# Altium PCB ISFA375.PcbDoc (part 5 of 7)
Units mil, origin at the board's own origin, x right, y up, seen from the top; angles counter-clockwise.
Board outline 5615 x 5520 mil, 6 copper layers (Top_SL, GND, POWER, Signal_Layer, GND2, Bottom_SL), stack 60.472 mil thick; 494 components, 307 nets, 1648 pads, 755 vias.
Unrouted connection lines stored in the file: 315.
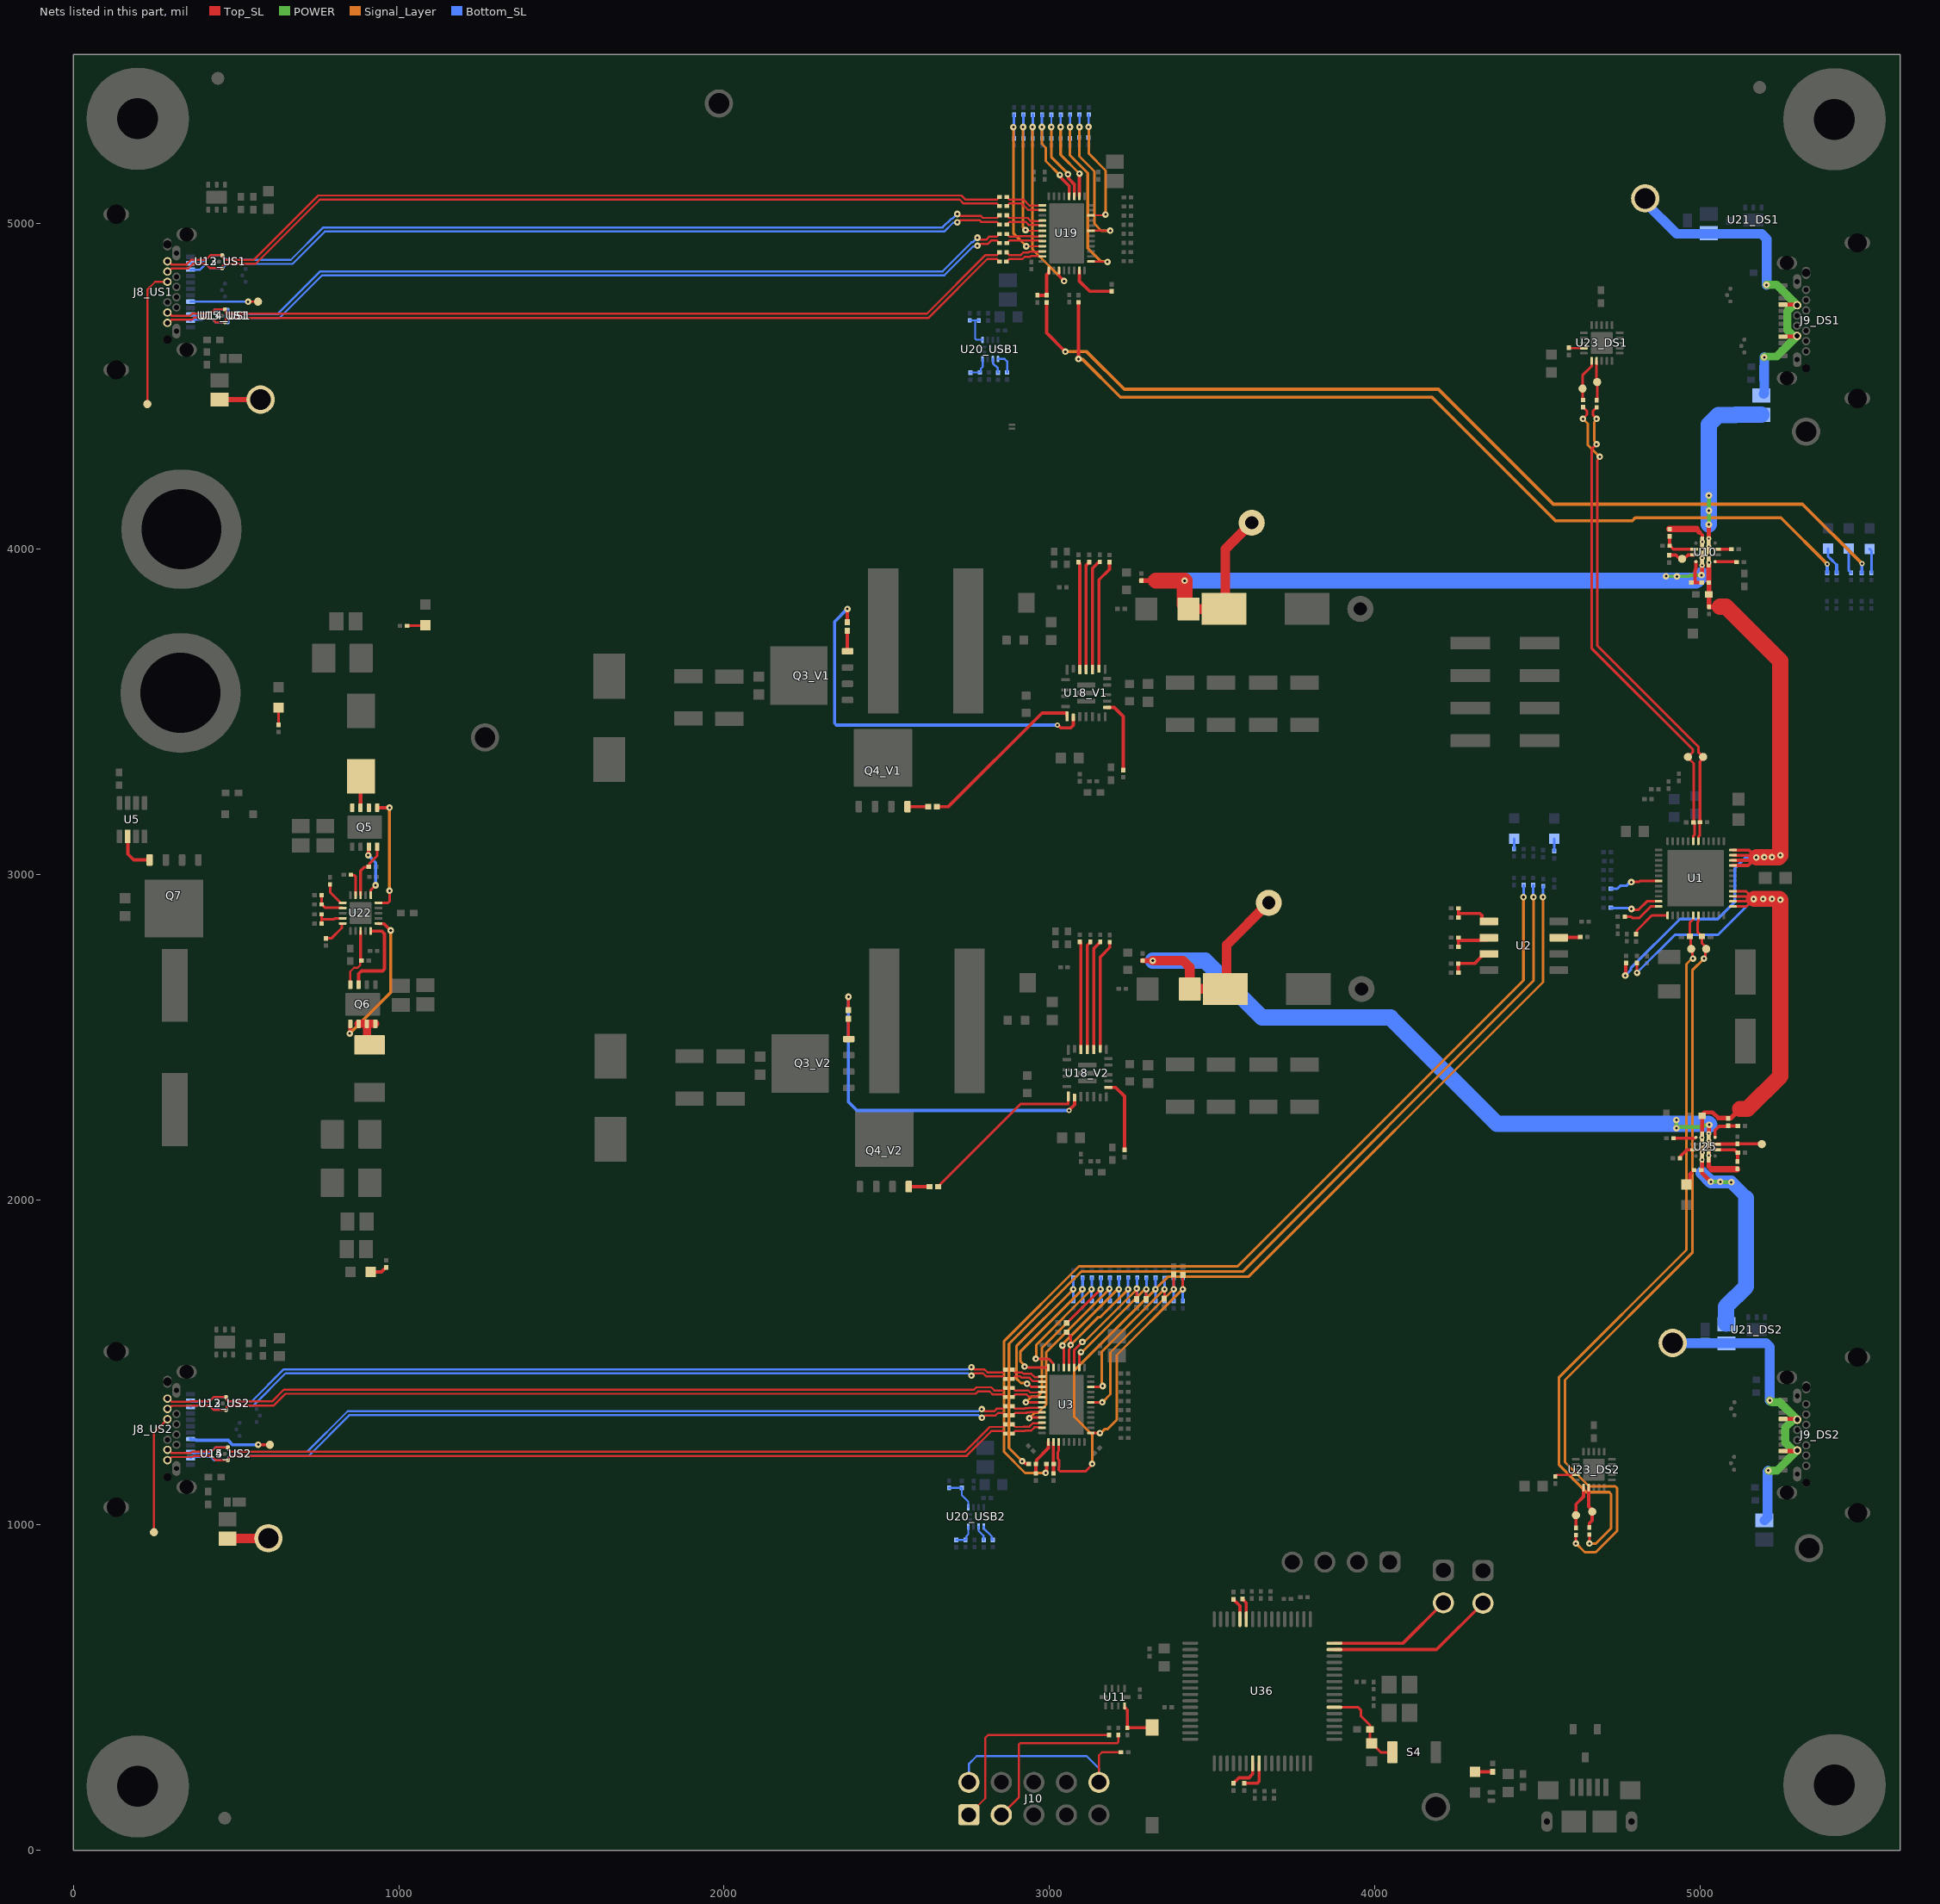
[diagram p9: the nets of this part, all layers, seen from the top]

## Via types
v1: diameter 20, hole 8, Top_SL to Bottom_SL, 628 vias
v2: diameter 19.68, hole 7.87, Top_SL to Bottom_SL, 66 vias
v3: diameter 16, hole 8, Top_SL to Bottom_SL, 23 vias
v4: diameter 16, hole 6, Top_SL to Bottom_SL, tented both sides, 16 vias
v5: diameter 137.8, hole 125.98, Top_SL to Bottom_SL, 8 vias
v6: diameter 50, hole 28, Top_SL to Bottom_SL, 8 vias
v7: diameter 28, hole 16, Top_SL to Bottom_SL, 6 vias

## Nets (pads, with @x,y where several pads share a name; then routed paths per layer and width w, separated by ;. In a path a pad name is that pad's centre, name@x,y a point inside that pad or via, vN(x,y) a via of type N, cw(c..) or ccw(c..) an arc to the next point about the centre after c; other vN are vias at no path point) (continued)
NetD2_2: D2.2 R2.2 | length 54.9
  Top_SL w10: D2.2@4957.96,2046.88 4968.71,2057.63 4968.71,2078.6 4981.41,2091.3 R2.2@4982.2,2091.3
NetD10_2: D10.2 R114.1 | length 52.4
  Top_SL w8: R114.1@630,3460.02 D10.2@630,3512.46
NetD11_2: D11.2 R115.1 | length 57.3
  Top_SL w8: R115.1@1025.51,3764.22 1080.05,3764.22 D11.2@1082.02,3766.19
NetD12_2: D12.2 R116.1 | length 53.3
  Top_SL w10: D12.2@913.97,1777.89 946.91,1777.89 958.91,1789.89 959.7,1789.89 961,1791.19 R116.1@961,1791.98
NetD15_2: D15.2 R110.1 | length 37.9
  Bottom_SL w8: R110.1@4551.61,3071.57 4551.61,3108.89 D15.2@4552,3109.27
NetD16_2: D16.2 R118.1 | length 31.2
  Bottom_SL w8: R118.1@4428.35,3078.21 D16.2@4428.35,3109.39
NetD17_2: D17.2 R156.1 | length 85.4
  Bottom_SL w8: D17.2@5393.39,4001.28 5393.39,3977.36 5399.01,3971.74 5399.43,3971.74 5420,3951.17
  Bottom_SL w10: R156.1@5420,3927.11 5420,3951.17
NetD18_2: D18.2 R158.1 | length 75
  Bottom_SL w8: D18.2@5521.25,4000.58 5526.89,3994.95 R158.1@5526.89,3927.9
NetD20_1: D20.1 R134.2 | length 55.1
  Top_SL w10: D20.1@4307.86,241.33 R134.2@4362.92,241.33
NetD21_2: D21.2 R173.1 | length 77.7
  Bottom_SL w8: D21.2@5456.79,4001.1 5456.79,3934.93 5461.53,3930.2 5462.31,3930.2 5464.61,3927.9 R173.1@5464.61,3927.11
NetJ10_1: J10.1 R155.2 | length 641.8
  Top_SL w6.5: J10.1@2752.24,109.26 2803,160.02 2803,345.98 2811.56,354.55 R155.2@3183.51,354.55
NetJ10_2: J10.2 J10.10 R161.2 | length 679.5
  Top_SL w6.5: J10.10@3152.24,209.26 3152.24,292.34 3161.45,301.56 R161.2@3220.06,301.56
  Bottom_SL w6: J10.2@2752.24,209.26 2752.24,265.48 2776.5,289.75 3114.67,289.75 3152.24,252.18 J10.10@3152.24,209.26
NetJ10_3: J10.3 R157.2 | length 568.5
  Top_SL w6.5: J10.3@2852.24,109.26 2906.68,163.71 2906.68,325.5 2910.49,329.31 3208.04,329.31 3211.85,333.12 R157.2@3211.85,354.55
NetJ13_2: J13.2 U36.47 | length 516.1
  Top_SL w10: U36.47@3875.82,617.15 4190.13,617.15 J13.2@4332.85,759.86
NetJ14_2: J14.2 U36.48 | length 386.6
  Top_SL w10: U36.48@3875.82,636.83 4087.03,636.83 J14.2@4211.08,760.88
NetL5_US1_2: L5_US1.2 TP9_US1.1 | length 126.2
  Top_SL w15: L5_US1.2@448.8,4459.47 TP9_US1.1@575.03,4459.47
NetL5_US2_2: L5_US2.2 TP9_US2.1 | length 125.7
  Top_SL w30: L5_US2.2@473.7,958.47 474.2,958.97 598.53,958.97 TP9_US2.1@599.03,959.47
NetL6_2: L6.2 Q5.6 Q5.7 Q5.8 | length 97.3
  Top_SL w12: Q5.7@882.31,3205.05 882.31,3300.5 L6.2@883.65,3301.83
NetL8_1: L8.1 Q6.6 Q6.7 Q6.8 | length 119.5
  Top_SL w25: Q6.6@876.37,2540.65 Q6.7@901.96,2540.65 ; L8.1@910.42,2475.87 901.96,2484.33 Q6.7@901.96,2540.65 ; Q6.8@927.55,2540.65 Q6.7@901.96,2540.65
NetQ3_V1_4: Q3_V1.4 R67_V1.2 | length 63.4
  Top_SL w10: R67_V1.2@2378.79,3749.19 2379.04,3748.94 2379.04,3686.25 Q3_V1.4@2379.29,3686
NetQ3_V2_4: Q3_V2.4 R67_V2.2 | length 63
  Top_SL w10: R67_V2.2@2382.08,2556.61 2382.08,2495 Q3_V2.4@2383.08,2494
NetQ4_V1_4: Q4_V1.4 R65_V1.2 | length 66
  Top_SL w10: Q4_V1.4@2563.83,3208.4 R65_V1.2@2629.87,3208.4
NetQ4_V2_4: Q4_V2.4 R65_V2.2 | length 66
  Top_SL w10: Q4_V2.4@2567.62,2040.4 R65_V2.2@2633.66,2040.4
NetQ5_3: Q5.3 U22.16 | length 166.8
  Top_SL w8: U22.16@913.97,2936.06 914.07,2936.16 914.07,2951.99 v1(928.72,2966.65)
  Top_SL w10: v1@907.72,3058.96 v1(906.09,3058.96) 907,3059.86 907,3084.06 Q5.3@907.91,3084.97
  Bottom_SL w10: v1(906.09,3058.96) 928.72,3036.33 v1(928.72,2966.65)
NetQ5_4: Q5.4 R14.1 U22.18 | length 177.9
  Top_SL w8: U22.18@882.47,2936.06 882.47,3010.93 894.27,3022.72 906.86,3022.72 R14.1@907.87,3023.72 908.65,3023.72 909.95,3025.02 909.95,3033.63 933.5,3057.17 Q5.4@933.5,3084.97
NetQ5_5: Q5.5 U22.15 | length 361.2
  Top_SL w8: U22.15@937.59,2912.44 966.55,2912.44 971.24,2917.13 v1(971.24,2949.51)
  Top_SL w10: Q5.5@933.5,3205.05 v1(971.24,3205.05)
  Signal_Layer w10: v1(971.24,2949.51) v1(971.24,3205.05)
NetQ6_3: Q6.3 U22.10 | length 273.3
  Top_SL w10: Q6.3@876.37,2660.73 876.37,2694.53 885.43,2703.59 950.24,2703.59 956.09,2709.45 956.09,2817.45 947.72,2825.83 U22.10@913.97,2825.83
NetQ6_4: Q6.4 R15.2 U22.8 | length 187
  Top_SL w6.5: Q6.4@850.78,2660.73 850.78,2701.22 862.69,2713.14 873.51,2713.14 881.59,2721.22 881.59,2732.04 884.29,2734.74 R15.2@885.43,2734.74
  Top_SL w10: U22.8@882.47,2825.83 882.47,2737.26 R15.2@884.64,2735.09
NetQ6_5: Q6.5 U22.11 | length 445.6
  Top_SL w10: v1(849.22,2511.03) 850,2511.81 850,2539.87 Q6.5@850.78,2540.65 ; U22.11@937.59,2849.45 938.65,2848.39 954.41,2848.39 v1(975.11,2827.69)
  Signal_Layer w10: v1(849.22,2511.03) 975.11,2636.93 v1(975.11,2827.69)
NetQ7_4: Q7.4 U5.6 | length 129.1
  Top_SL w10: U5.6@166.79,3117.06 166.79,3062.71 184.92,3044.59 Q7.4@233.84,3044.59 Q7.4@233.72,3044.7
NetR5_2: R5.2 U1.43 | length 157
  Top_SL w8: v1(4788.78,2976.5) 4789.65,2977.38 4812.03,2977.38 4814.78,2980.13 U1.43@4872.83,2980.13
  Bottom_SL w8: R5.2@4725.89,2955.87 4745.98,2955.87 4754.98,2964.87 4773.9,2964.87 4785.53,2976.5 v1(4788.78,2976.5)
NetR11_2: R11.2 U1.47 | length 160
  Top_SL w8: v1(4788.97,2893.86) 4791.27,2891.57 4811.57,2891.57 4837.07,2917.07 U1.47@4872.68,2917.07
  Bottom_SL w8: R11.2@4725.89,2897.87 4727.89,2895.87 4786.97,2895.87 v1(4788.97,2893.86)
NetR16_1: R16.1 R112.2 U22.2 | length 97.7
  Top_SL w8: R112.2@762.72,2936.06 R16.1@762.72,2907.52 764.02,2906.22 764.81,2906.22 773.59,2897.44 826.61,2897.44 U22.2@827.35,2896.69
NetR17_1: R17.1 R25.2 U2.1 | length 138.8
  Top_SL w10: R17.1@4257.24,2867.57 4257.24,2880.08 ; R25.2@4257.24,2895.57 4257.24,2880.08 ; U2.1@4350.93,2855.52 4336.06,2855.52 4329.25,2862.33 4329.25,2874.23 4323.39,2880.08 4257.24,2880.08
NetR18_1: R18.1 R26.2 U2.2 | length 125.3
  Top_SL w10: 4257.02,2797.28 4321.53,2797.28 4322.97,2798.71 4344.12,2798.71 U2.2@4350.93,2805.52 ; R18.1@4257.24,2777.52 4257.24,2789.33 R26.2@4257.24,2805.52
NetR19_1: R19.1 R27.2 U2.3 | length 165.1
  Top_SL w10: R19.1@4256.76,2725.87 4256.89,2725.73 4256.89,2698.27 4257.16,2698 R27.2@4257.94,2698 ; R27.2@4257.81,2697.87 R27.2@4257.02,2697.87 4257.02,2726.13 4306.77,2726.13 4327.39,2746.76 4327.39,2748.71 4334.2,2755.52 U2.3@4350.93,2755.52
NetR20_2: R20.2 U2.7 | length 67.1
  Top_SL w10: U2.7@4565.5,2805.52 4566.52,2806.54 4630.69,2806.54 R20.2@4631.71,2807.56
NetR23_1: R23.1 R111.2 U22.4 | length 96.6
  Top_SL w8: R111.2@762.63,2849.03 762.63,2865.76 ; R23.1@762.63,2877.58 762.63,2865.76 ; U22.4@827.35,2865.19 803.82,2865.19 800.07,2861.44 766.96,2861.44 762.63,2865.76
NetR24_2: R24.2 U22.19 | length 74.3
  Top_SL w8: R24.2@852.73,2999.09 855.03,2996.8 864.34,2996.8 866.72,2994.41 U22.19@866.72,2936.06
NetR28_2: R28.2 U22.1 | length 76.1
  Top_SL w8: R28.2@788.77,2969.17 788.77,2945.28 821.61,2912.44 U22.1@827.35,2912.44
NetR30_2: R30.2 U36.23 | length 104.2
  Top_SL w10: R30.2@3566.07,206.17 3566.07,206.96 3582.37,223.26 3613.57,223.26 3624.83,234.52 U36.23@3624.83,267.74
NetR45_1: R45.1 U36.59 | length 66.9
  Top_SL w10: R45.1@3594,772.98 3594,772.19 3605.15,761.04 U36.59@3605.15,710.65
NetR46_2: R46.2 U36.24 | length 103.6
  Top_SL w10: R46.2@3599.04,206.17 3638.66,206.17 3644.52,212.03 U36.24@3644.52,267.74
NetR47_1: R47.1 U36.60 | length 69.4
  Top_SL w10: R47.1@3566,771.98 3566,771.19 3585.46,751.73 U36.60@3585.46,710.65
NetR63_2: R63.2 R64.2 U10.4 | length 95.2
  Top_SL w10: R64.2@4973.36,3896.96 4988.81,3896.96 ; 4987.4,3896.96 4984.52,3899.84 4984.52,3935.06 4987.4,3937.94 U10.4@4987.4,3961.38 ; 4988.81,3896.88 5001.68,3896.88 R63.2@5001.76,3896.81
NetR65_V1_1: R65_V1.1 U18_V1.1 | length 527.2
  Top_SL w10: R65_V1.1@2653.89,3208.4 2689.76,3208.4 2977.69,3496.33 3052.56,3496.33 3053.13,3495.76 U18_V1.1@3053.13,3487.3
NetR65_V2_1: R65_V2.1 U18_V2.1 | length 529.9
  Top_SL w8: R65_V2.1@2657.68,2040.4 2658.46,2040.4 2662.73,2044.67 2662.73,2045.46 2911.02,2293.74 3057.88,2293.74 3058.08,2293.94 U18_V2.1@3058.08,2318
NetR67_V1_1: R67_V1.1 U18_V1.2 | length 1175.4
  Top_SL w10: R67_V1.1@2378.79,3775.17 v1(2378.79,3815.9) ; v3(3024.6,3459.29) 3026.22,3459.29 3035.35,3450.16 3065.34,3450.16 3073.41,3458.24 3073.41,3482.47 U18_V1.2@3073.49,3482.55
  Bottom_SL w10: v1(2378.79,3815.9) 2339.63,3776.73 2339.63,3465.15 2345.48,3459.29 v3(3024.6,3459.29)
NetR67_V2_1: R67_V2.1 U18_V2.2 | length 1101.3
  Top_SL w10: R67_V2.1@2382.08,2582.59 v1(2382.08,2623.86) ; v3(3060.54,2274.16) 3060.54,2275.78 3077.2,2292.44 3077.2,2314.47 U18_V2.2@3077.28,2314.55
  Bottom_SL w10: v1(2382.08,2623.86) 2382.08,2300.58 2408.49,2274.16 v3(3060.54,2274.16)
NetR71_V1_1: R71_V1.1 U18_V1.14 | length 341
  Top_SL w10: U18_V1.14@3152.23,3632.16 3152.23,3905.42 3184.46,3937.65 R71_V1.1@3184.46,3959.82
NetR71_V2_1: R71_V2.1 U18_V2.14 | length 340
  Top_SL w10: U18_V2.14@3156.02,2464.16 3156.02,2745.88 3185.54,2775.41 R71_V2.1@3185.54,2791.98
NetR73_V1_2: R73_V1.2 U18_V1.8 | length 225.6
  Top_SL w10: U18_V1.8@3177.33,3513.06 3199.63,3513.06 3226.92,3485.77 R73_V1.2@3226.92,3321.02
NetR73_V2_2: R73_V2.2 U18_V2.8 | length 225.6
  Top_SL w10: U18_V2.8@3181.12,2345.06 3203.42,2345.06 3230.71,2317.77 R73_V2.2@3230.71,2153.02
NetR75_V1_2: R75_V1.2 U18_V1.15 | length 338.9
  Top_SL w10: U18_V1.15@3132.54,3629.7 3132.54,3940.49 R75_V1.2@3152.39,3960.34
NetR75_V2_2: R75_V2.2 U18_V2.15 | length 338.9
  Top_SL w10: U18_V2.15@3136.33,2461.7 3136.33,2771.71 3156.18,2791.55 R75_V2.2@3156.18,2792.34
NetR76_V1_2: R76_V1.2 U18_V1.16 | length 334.5
  Top_SL w10: U18_V1.16@3112.86,3629.7 3112.86,3950.14 3122.27,3959.55 R76_V1.2@3122.27,3960.34
NetR76_V2_2: R76_V2.2 U18_V2.16 | length 334.5
  Top_SL w10: U18_V2.16@3116.65,2461.7 3116.65,2782.14 3126.06,2791.55 R76_V2.2@3126.06,2792.34
NetR78_2: R78.2 U19.27 | length 141.4
  Top_SL w10: U19.27@3092.34,4856.27 3092.34,4823.79 3123.53,4792.6 R78.2@3188.31,4792.6
NetR90_USB1_1: R90_USB1.1 R91_USB1.1 U20_USB1.6 | length 73.5
  Bottom_SL w6: R90_USB1.1@2757.5,4542.64 2757.69,4542.83 2785.81,4542.83 2788.84,4545.86 2788.84,4554.3 2794.8,4560.27 U20_USB1.6@2794.8,4584.21
NetR90_USB2_1: R90_USB2.1 R91_USB2.1 U20_USB2.6 | length 73.5
  Bottom_SL w6: R90_USB2.1@2713.5,953.94 2713.7,954.13 2741.81,954.13 2744.84,957.16 2744.84,965.6 2750.81,971.57 U20_USB2.6@2750.81,995.52
NetR103_USB1_2: R103_USB1.2 R104_USB1.2 U20_USB1.9 | length 109.2
  Bottom_SL w6: R104_USB1.2@2755,4702.98 2755.19,4702.79 2771.46,4702.79 ; R103_USB1.2@2783.27,4702.6 2783.08,4702.79 2771.46,4702.79 ; U20_USB1.9@2794.8,4643.27 2774.97,4643.27 2771.46,4646.78 2771.46,4702.79
NetR103_USB2_2: R103_USB2.2 R104_USB2.2 U20_USB2.9 | length 106.8
  Bottom_SL w6: R104_USB2.2@2691.92,1114.09 2730.93,1114.09 R103_USB2.2@2730.93,1113.9 2730.93,1091.72 2750.81,1071.85 U20_USB2.9@2750.81,1054.57
NetR105_1: R105.1 R107.1 U10.2 | length 108.2
  Top_SL w10: R105.1@4906.58,4039.08 R107.1@4906.6,4010.1 4907.39,4010.1 4917.73,3999.76 U10.2@4981.5,3999.76
NetR106_2: R106.2 TP15.1 U10.3 | length 86.6
  Top_SL w10: R106.2@4905.66,3982.05 4906.58,3981.13 4907.5,3982.05 4926,3982.05 4938.05,3970 TP15.1@4945,3970 4950.95,3970 4963,3982.05 U10.3@4981.5,3982.05
NetR108_2: R108.2 U1.1 | length 125.1
  Top_SL w8: R108.2@4803.6,2817.03 4805.9,2819.33 4805.9,2827.9 4851.71,2873.71 U1.1@4900.23,2873.71
NetR109_2: R109.2 U1.48 | length 122.5
  Top_SL w8: R109.2@4766.33,2870.19 4787.97,2870.19 4791.88,2866.28 4813.28,2866.28 4848.32,2901.32 U1.48@4872.68,2901.32
NetR113_2: R113.2 U22.5 | length 78.3
  Top_SL w8: R113.2@775.83,2803.2 792.64,2803.2 824.75,2835.31 824.75,2848.39 825.82,2849.45 U22.5@827.35,2849.45
NetR117_V1_2: R117_V1.2 U18_V1.17 | length 332.2
  Top_SL w10: R117_V1.2@3089.37,3960.34 3089.37,3959.55 3093.17,3955.75 U18_V1.17@3093.17,3629.7
NetR117_V2_2: R117_V2.2 U18_V2.17 | length 332.2
  Top_SL w10: R117_V2.2@3093.16,2792.34 3093.16,2791.55 3096.96,2787.75 U18_V2.17@3096.96,2461.7
NetR139_2: R139.2 U10.9 | length 44.3
  Top_SL w10: U10.9@5052.36,3999.76 R139.2@5096.66,3999.76
NetR144_USB1_1: R144_USB1.1 U20_USB1.4 | length 48.1
  Bottom_SL w6.5: U20_USB1.4@2826.3,4584.21 2826.36,4584.16 2826.36,4570.86 2841.55,4555.67 2841.55,4543.07 R144_USB1.1@2841.98,4542.64
NetR144_USB2_1: R144_USB2.1 U20_USB2.4 | length 48.1
  Bottom_SL w6.5: U20_USB2.4@2782.3,995.52 2782.36,995.46 2782.36,982.16 2797.55,966.97 2797.55,954.37 R144_USB2.1@2797.98,953.94
NetR145_USB1_1: R145_USB1.1 U20_USB1.3 | length 64.7
  Bottom_SL w6.5: U20_USB1.3@2842.05,4584.21 2842.73,4584.21 2862.45,4584.21 2869.95,4576.71 R145_USB1.1@2869.95,4543.02
NetR145_USB2_1: R145_USB2.1 U20_USB2.3 | length 52.7
  Bottom_SL w6.5: U20_USB2.3@2798.05,995.52 2798.74,994.83 2798.74,988.92 2822.91,964.75 2822.91,957.38 R145_USB2.1@2825.96,954.33
NetR149_1: R149.1 R150.1 U3.21 | length 113.4
  Top_SL w10: R150.1@2958.17,1158.76 R149.1@2958.2,1187.74 ; R149.1@2958.2,1187.74 2958.98,1187.74 2960.28,1189.04 2960.28,1199.92 2997.12,1236.75 U3.21@2997.12,1255.56
NetR151_1: R151.1 R152.1 U3.22 | length 96.9
  Top_SL w10: U3.22@3012.12,1254.82 3012.12,1230.54 3011.8,1230.22 3011.8,1188.8 3012.87,1187.74 3012.75,1187.62 3012.75,1159.21 R151.1@3012.31,1158.76
NetR153_1: R153.1 R154.1 U19.21 | length 108
  Top_SL w6: R154.1@2963.31,4780.02 R154.1@2963.47,4780.19 ; R153.1@2991.29,4780.19 R153.1@2991.45,4780.35
  Top_SL w10: R154.1@2963.47,4780.19 R153.1@2991.29,4780.19 ; R153.1@2991.45,4780.35 2991.45,4843.95 2994.96,4847.46 2996.91,4847.46 2997.85,4848.4 U19.21@2997.85,4856.27
NetR159_DS1_2: R159_DS1.2 TP13_DS1.1 U23_DS1.12 | length 121.9
  Top_SL w8: R159_DS1.2@4682.22,4457.77 4683.89,4459.44 TP13_DS1.1@4683.89,4513.37 4682.22,4515.04 U23_DS1.12@4682.22,4578.25
NetR159_DS2_2: R159_DS2.2 TP13_DS2.1 U23_DS2.12 | length 129.9
  Top_SL w10: U23_DS2.12@4657.93,1115.2 4657.93,1058.53 4657.54,1058.14 4657.54,1056.37 4668.29,1045.63 4668.29,1013.6 4659.9,1005.21 R159_DS2.2@4659.9,993.4
NetR160_DS1_2: R160_DS1.2 TP14_DS1.1 U23_DS1.11 | length 132.2
  Top_SL w8: R160_DS1.2@4640.83,4458.29 4638.83,4460.29 4638.83,4534.01 4666.47,4561.65 U23_DS1.11@4666.47,4578.25
NetR160_DS2_2: R160_DS2.2 TP14_DS2.1 U23_DS2.11 | length 133.4
  Top_SL w10: R160_DS2.2@4618.56,991.63 TP14_DS2.1@4618.56,1030.36 4618.56,1063.86 4642.18,1087.48 U23_DS2.11@4642.18,1115.2
NetR162_2: R162.2 S1.2 U11.9 | length 141.5
  Top_SL w10: U11.9@3232.6,438.56 3239.85,431.3 R162.2@3239.85,376.6 3240.64,377.38 S1.2@3316.08,377.38
NetR163_DS1_2: R163_DS1.2 U23_DS1.9 | length 46.8
  Top_SL w6.5: R163_DS1.2@4597.08,4620.18 4599.05,4618.21 4641.75,4618.21 U23_DS1.9@4642.7,4617.27
NetR163_DS2_2: R163_DS2.2 U23_DS2.9 | length 66.1
  Top_SL w6.5: R163_DS2.2@4554.97,1149.54 4554.97,1150.32 4559.22,1154.57 U23_DS2.9@4618.56,1154.57
NetR164_1: R164.1 U10.7 | length 66.6
  Top_SL w10: U10.7@5046.46,3961.38 5111.4,3961.38 R164.1@5112.58,3960.2
NetR166_2: R166.2 R167.2 U25.4 | length 98.5
  Top_SL w10: U25.4@5046.37,2191.53 5046.37,2213.52 5058.18,2225.34 5084.96,2225.34 5086.26,2226.63 R166.2@5086.26,2227.42 5086.75,2226.93 5115.75,2226.93 R167.2@5116.23,2226.45
NetR168_1: R168.1 R170.1 U25.2 | length 94.5
  Top_SL w10: U25.2@5052.28,2153.14 5106.57,2153.14 5113.97,2145.75 5114.76,2145.75 5115.66,2144.84 5115.66,2117.71 R168.1@5115.27,2117.32
NetR169_2: R169.2 TP16.1 U25.3 | length 138.5
  Top_SL w10: U25.3@5052.28,2170.86 5052.35,2170.94 5114.42,2170.94 R169.2@5115.27,2171.78 5189.23,2171.78 TP16.1@5190.08,2170.94
NetR171_2: R171.2 U25.9 | length 55.9
  Top_SL w10: R171.2@4939.56,2127.55 4939.56,2133.42 4959.28,2153.14 U25.9@4981.41,2153.14
NetR172_1: R172.1 U25.7 | length 69.8
  Top_SL w8: R172.1@4918.54,2189.07 4984.31,2189.07 4986.77,2191.53 U25.7@4987.32,2191.53
PA_CC1: C1.2 R159_DS1.1 TP1.1 U1.31 | length 1493.6
  Top_SL w8: v1(4682.22,4322.25) 4666.47,4306.5 4666.47,3695.53 4978.6,3383.4 4978.6,3376.77 TP1.1@4963,3361.17 4963,3359.14 4980.81,3341.33 C1.2@4980.81,3160 ; v1(4682.22,4400.49) 4670.41,4412.3 4670.41,4423.92 4680.13,4433.64 4680.92,4433.64 4682.22,4434.94 R159_DS1.1@4682.22,4435.73 ; U1.31@4979.11,3109.98 4979.11,3118.33 4983.78,3123.01 C1.2@4983.78,3160
  Signal_Layer w8: v1(4682.22,4322.25) 4682.22,4324.96 4675,4332.18 4675,4390.57 4682.22,4397.78 v1(4682.22,4400.49)
PA_CC2: C2.2 R160_DS1.1 TP2.1 U1.30 | length 1510.7
  Top_SL w8: v1(4640.14,4400.49) 4652.64,4412.99 4652.64,4424.44 4642.92,4434.16 4642.13,4434.16 4640.83,4435.46 R160_DS1.1@4640.83,4436.25 ; v1(4691.93,4284) 4691.93,4281.05 4684.19,4273.31 4684.19,3702.94 4995.72,3391.4 4995.72,3374.95 TP2.1@5009.5,3361.17 5009.5,3356.57 4999.87,3346.93 C2.2@4999.87,3160.63 4998.63,3159.39 4998.63,3119.47 4994.94,3115.78 U1.30@4994.87,3102.17 U1.30@4994.87,3102.17
  Signal_Layer w8: v1(4640.14,4400.49) 4655,4385.63 4655,4319.93 4690.93,4284 v1(4691.93,4284)
PA_PPHV: C52_V1.1 R69_V1.2 R77_V1.2 R105.2 TP7_V1.1 U10.5 | length 2770.6
  Top_SL w10: R105.2@4906.58,4061.13 R105.2@4906.58,4061.91 ; 4998.1,4051.38 4998.9,4052.18 ; 4998.93,4052.18 5003.64,4046.92 5004.45,4046.01 5007,4043.16 v4(5007,4022.17) 5007,4020.54 5007.09,4020.45 5007,4020.36 v4(5007,3998)
  Top_SL w12: v1(5004.52,3919.91) 5004.52,3922.07 5007.09,3924.64 U10.5@5007.09,3949.66 ; v4(5006.52,3949.93) 5006.99,3949.93 U10.5@5006.99,3972.59 ; v4(5006.52,3972.59) U10.5@5006.99,3972.59 ; v4(5007,3998) U10.5@5006.99,3972.59
  Top_SL w15: R77_V1.2@3282.73,3902.86 3314.57,3902.86 ; 4989.23,4061.91 4989.59,4061.56 4989.59,4059.89 4998.1,4051.38
  Top_SL w20: R105.2@4906.58,4061.91 4989.23,4061.91
  Top_SL w30: R69_V1.2@3427.9,3815.9 C52_V1.1@3536.79,3815.9 3540.74,3819.85 3540.74,3999.62 TP7_V1.1@3622,4080.88
  Top_SL w50: 3327.36,3902.86 v1(3415.66,3902.86) 3415.66,3830.11 3419.44,3826.33 3419.44,3824.37 R69_V1.2@3427.9,3815.9
  POWER w10: v1(4895.58,3916.51) v1@4895.79,3916.3 ; v1@4896.5,3915.59 v1@4895.79,3916.3 ; v4(5007,4022.17) 5005.85,4021.02 5005.85,3921.23 v1(5004.52,3919.91) 4969.64,3919.91 4965.82,3916.09 v1(4929.02,3916.09) 4928.8,3916.3 v1@4895.79,3916.3
  Bottom_SL w10: v1(5004.52,3919.91) 5005.85,3921.23 v4@5005.85,3949.93 ; v4(5006.52,3949.93) v4(5006.52,3972.59) ; v4@5007,3973.07 v4(5007,3998) v4(5007,4022.17)
  Bottom_SL w50: v1(3415.66,3902.86) 4987.48,3902.86 v1(5004.52,3919.91)
PA_VBUS: C3.1 L2_DS1.1 R1.1 R63.1 R133.2 U1.21 U1.22 U1.23 U1.24 U10.6 | length 2956.1
  Top_SL w10: v1(4770.3,2689.07) 4771.78,2690.54 4771.78,2726.07 R133.2@4773.08,2727.37 ; U1.21@5101.17,3027.37 5148.37,3027.37 v1(5173,3052) 5150.39,3074.61 U1.24@5101.17,3074.61 ; U1.22@5101.17,3043.12 5161.95,3043.12 ; U1.23@5101.17,3058.87 v1@5166.13,3058.87
  Top_SL w12: U10.6@5026.77,3957.86 v4(5027.49,3958.57) ; U10.6@5026.77,3990.66 U10.6@5026.77,3990.91 v4(5026.77,4008.07) 5026.77,4031.91 U10.6@5026.87,4032 ; U10.6@5027.02,3958.82 U10.6@5027.02,3990.66 ; v1(5027,4075.39) 5027.04,4075.34 5027.04,4031.95 v4(5027.09,4031.91) ; 5053.31,3822.61 5057.28,3826.58
  Top_SL w15: R63.1@5027.02,3897 U10.6@5027.02,3951.16 ; C3.1@5027.22,3861 C3.1@5027.49,3861 ; R63.1@5027.49,3896.7 C3.1@5027.49,3861 ; 5053.31,3822.61 R1.1@5027.49,3822.61 C3.1@5027.49,3861
  Top_SL w50: 5061.25,3822.61 5080.32,3822.61 5246.87,3656.06 v1(5246.87,3058.72) 5240.98,3052.82 v1(5221,3052.82) v1(5197.41,3052.82) v1@5173.82,3052.82
  POWER w12: v1(5027.09,4165) 5027.29,4164.8 5027.29,4118.2 5027.24,4118.15 5027.24,4075.63 v1(5027,4075.39) 5027.04,4075.34 5027.04,4032.15 5027.29,4031.91 5027.29,3958.77 v4(5027.49,3958.57)
  Bottom_SL w8: v1(4770.3,2689.07) 4787.19,2705.95 4787.19,2711.47 4938.45,2862.73 5054.4,2862.73 5107.08,2915.42 5107.08,3018.63 5140.45,3052 v1(5173,3052)
  Bottom_SL w12: v1(5027,4075.39) 5027.24,4075.14 5027.24,3958.82 v4(5027.49,3958.57)
  Bottom_SL w50: v1(5027,4075.39) 5027.49,4075.87 v1(5027.49,4118) 5027.49,4164.6 v1(5027.09,4165) 5027.09,4382.9 5056.38,4412.19 5108.73,4412.19 5109.25,4412.71 L2_DS1.1@5188.87,4412.71
  other v4: 5027,3981
PB_CC1: C6.1 R159_DS2.1 TP4.1 U1.6 | length 2285.3
  Top_SL w8: v1(4659.9,943.55) R159_DS2.1@4659.9,970.57 ; v1(4978.6,2741.02) 4978.6,2744.27 4976.25,2746.62 4976.25,2767.75 4971,2773 4971,2808 C6.1@4969,2810 4969,2852.13 4979.13,2862.25 U1.6@4979.13,2873.83
  Signal_Layer w8: v1(4659.9,943.55) 4680.46,943.55 4726.68,989.77 4726.68,1095.35 4720.92,1101.11 4650.37,1101.11 4566.78,1184.7 4566.78,1454.55 4957.96,1845.72 4957.96,2723.79 4963.61,2729.45 4963.79,2729.45 4975.36,2741.02 v1(4978.6,2741.02)
PB_CC2: C7.1 R160_DS2.1 TP5.1 U1.7 | length 2387.9
  Top_SL w8: v1(4618.56,943.55) R160_DS2.1@4618.56,969.58 ; U1.7@4994.87,2873.83 4994.81,2873.76 4994.81,2855.22 4992.12,2852.52 4992.12,2823.1 5006.01,2809.21 5006.01,2788.59 5019,2775.6 TP5.1@5019,2771 5016.13,2768.13 5016.13,2747.64 5012.21,2743.72 v1(5012.21,2741.02)
  Signal_Layer w8: v1(4618.56,943.55) 4645.68,916.43 4679.43,916.43 4744.55,981.55 4744.55,1114.14 4739.87,1118.83 4659.23,1118.83 4585,1193.06 4585,1445.82 4976.17,1837 4976.17,2704.98 v1(5012.21,2741.02)
PB_PPHV: C52_V2.1 R69_V2.2 R77_V2.2 R168.2 TP7_V2.1 U25.5 | length 3111.4
  Top_SL w12: 5027,2102.4 v4(5027,2135.87) 5027.59,2136.46 v4(5027.59,2158.05) 5027.5,2158.15 5027.5,2181.48 5026.95,2182.03 v4(5027,2203) v4(5027,2203) 5027.61,2203.61 5027.61,2229.84 v1(5028.32,2230.55) ; R168.2@5114.97,2094.18 5115.27,2094.48 R168.2@5115.27,2095.27
  Top_SL w15: R77_V2.2@3286.51,2734.86 v1(3317.72,2734.86) ; 5027,2102.4 5035.22,2094.18
  Top_SL w20: 5035.22,2094.18 R168.2@5114.18,2094.18
  Top_SL w30: v1(3317.72,2734.86) 3411.09,2734.86 3431.69,2714.26 R69_V2.2@3431.69,2647.9 C52_V2.1@3540.57,2647.9 3544.53,2651.85 3544.53,2782.95 TP7_V2.1@3674.46,2912.88
  POWER w12: v1(4927.2,2244.94) v1(4927.2,2219.95) 4929.37,2219.95 4933.42,2224.01 5009.2,2224.01 5014.23,2229.04 5026.81,2229.04 v1(5028.32,2230.55) 5027.66,2229.89 5027.66,2203 5027.66,2181.99 5027.66,2158.05 5027.66,2136.53 v4(5027,2135.87)
  Bottom_SL w12: v4(5027,2135.87) 5027.3,2136.16 5027.3,2157.76 v4(5027.59,2158.05) 5027.25,2158.4 5027.25,2181.65 v4(5026.91,2181.99) 5026.95,2182.04 v4(5027,2203) v4(5027,2203) 5027.66,2203.66 5027.66,2229.89 v1(5028.32,2230.55)
  Bottom_SL w50: v1(3317.72,2734.86) 3479.14,2734.86 3653.73,2560.27 4048.74,2560.27 4376.06,2232.94 5025.92,2232.94 v1(5028.32,2230.55)
PB_VBUS: C5.1 L2_DS2.1 R2.1 R146.2 R166.1 U1.13 U1.14 U1.15 U1.16 U25.6 | length 2789.8
  Top_SL w8: R146.2@4805.82,2727.39 4806,2727.2 4806,2698.05 v1(4806.19,2697.87) ; U1.13@5101.13,2901.32 5142.21,2901.32 v1@5158.03,2917.13 ; U1.14@5101.17,2917.13 v1@5158.03,2917.13 ; U1.15@5101.13,2932.82 5146.36,2932.82 5149.74,2931.77 v1@5161.13,2926.16 ; U1.16@5101.13,2948.57 5140.73,2948.57 v1@5161.79,2927.5 ; v1(5165.09,2924.2) v1@5158.03,2917.13
  Top_SL w12: v4(5006.32,2123.13) 5006.32,2082.03 v1(5033.34,2055) ; U25.6@5006.99,2123.13 5006.99,2145.31 U25.6@5007,2162 U25.6@5007,2191.26 ; U25.6@5007.08,2194.85 5007.08,2192.02 v4(5006.32,2191.26) 5006.32,2261.66 5013.34,2268.69 5038.59,2268.69 5056.43,2250.85
  Top_SL w15: 5056.43,2250.85 5094.94,2250.85 5123.1,2279
  Top_SL w25: v1(5165.09,2924.2) v1@5165.71,2924.82 ; v1@5244.05,2924.82 v1(5246.87,2922)
  Top_SL w50: 5123.1,2279 5146,2279 5246.87,2379.87 v1(5246.87,2922) ; v1@5165.71,2924.82 v1(5193.98,2924.82) v1(5221,2924.82) v1@5244.05,2924.82
  POWER w12: v4(5006.32,2123.13) 5006.32,2082.03 v1(5033.34,2055) v1(5062.51,2055) 5063.05,2054.46 5095.54,2054.46 v1(5096.08,2053.92) ; v4@5006.32,2168.74 v4(5006.32,2191.26) ; v4@5006.91,2123.72 v4@5006.91,2168.65
  Bottom_SL w8: v1(4806.19,2697.87) 4922.78,2814.46 5055.35,2814.46 5142.48,2901.59 v1(5165.09,2924.2)
  Bottom_SL w12: 5006.32,2082.03 v4(5006.32,2123.13) v4(5006.32,2191.26) ; L2_DS2.1@5079.69,1618.95 L2_DS2.1@5081.11,1617.53
  Bottom_SL w40: 5006.32,2082.03 v1(5033.34,2055) v1(5062.51,2055) 5095,2055 v1(5096.08,2053.92) 5139,2011
  Bottom_SL w50: L2_DS2.1@5079.69,1618.95 5079.69,1671.05 5141.47,1732.83 5141.47,2005
  other v4: 5006.91,2145.31 5006.82,2168.74
RD1_AEQCFG: R85.1 R99.2 U19.23 | length 625.7
  Top_SL w8: U19.23@3029.35,4856.27 3029.35,4839.88 v1(3045.09,4824.13)
  Signal_Layer w8: v1(2948.06,5297.31) 2948.06,4921.16 v1(3045.09,4824.13) ; v1@2951.5,5297.31 v1@2951.5,5297.66
  Bottom_SL w8: R99.2@2948.74,5262.69 2948.4,5263.04 2948.4,5296.97 v1(2948.06,5297.31) 2948.52,5297.78 2948.52,5334.85 R85.1@2948.99,5335.31
RD1_CEQ0: R83.1 R97.2 U19.38 | length 409.1
  Top_SL w6: U19.38@3127.77,5025.56 3127.96,5025.75 3170.35,5025.75 v1(3172.66,5028.07)
  Signal_Layer w8: v1(3119.95,5297.93) 3120.95,5296.93 3120.95,5215.65 3172.76,5163.84 3172.76,5028.17 v1(3172.66,5028.07)
  Bottom_SL w6: R97.2@3119.95,5264.69 v1(3119.95,5297.93) 3120.45,5298.43 3120.45,5335.14 R83.1@3120.95,5335.64
RD1_CEQ1: R84.1 R98.2 U19.29 | length 598.2
  Top_SL w6: U19.29@3127.77,4883.83 3155.73,4883.83 3156.68,4882.88 3178.44,4882.88 v1(3178.68,4882.64)
  Signal_Layer w8: v1(3063.32,5297.31) 3063.32,5210.07 3117.89,5155.5 3117.89,4924.55 3157.5,4884.94 3176.39,4884.94 v1(3178.68,4882.64)
  Bottom_SL w6: R98.2@3062.88,5262.69 3063.26,5263.06 3063.26,5335.26 R84.1@3063.63,5335.64
RD1_EN: R135.1 R140.2 | length 2771.4
  Top_SL w10: v1(3089.37,4584.16) 3089.61,4584.39 R140.2@3089.61,4758.67
  Signal_Layer w10: v1(3089.37,4584.16) 3091.03,4582.49 3103.06,4582.49 3218.55,4467 4176,4467 4555.82,4087.18 4792.2,4087.18 4801.09,4096.08 5248.92,4096.08 v3(5390.72,3954.28)
  Bottom_SL w10: R135.1@5390.72,3927.11 v3(5390.72,3954.28)
RD1_EQCFG: R86.1 R100.2 U19.3 | length 314.9
  Top_SL w10: v1(3057,5151.88) 3058.91,5149.96 3058.91,5139.17 3076.59,5121.49 U19.3@3076.59,5084.62
  Signal_Layer w8: v1(3005.69,5297.31) 3005.69,5205.4 3057,5154.09 v1(3057,5151.88)
  Bottom_SL w6: R100.2@3005.81,5262.69 3006.06,5262.94 3006.06,5335.06 R86.1@3006.31,5335.31
RD1_FLIP: R128.1 R153.2 | length 2922.5
  Top_SL w10: R153.2@2991.45,4758.3 2991.45,4664.45 v1(3049.05,4606.86)
  Signal_Layer w10: v1(3049.05,4606.86) 3065.95,4606.86 3114.41,4606.86 3230.26,4491 4195.84,4491 4548.84,4138 5314.87,4138 v3(5498,3954.87)
  Bottom_SL w10: R128.1@5497,3927.11 5497.5,3927.61 5497.5,3954.37 v3(5498,3954.87)
RD1_MODE: R80.1 R94.2 U19.17 | length 507.3
  Top_SL w6: v1(2929.06,4930.7) 2929.25,4930.89 2977.98,4930.89 U19.17@2978.16,4931.08
  Signal_Layer w8: v1(2889,5297) 2889,4970.76 v1(2929.06,4930.7)
  Bottom_SL w8: v1(2889,5297) 2890.12,5297 2890.34,5297.22 2890.34,5333.98 R80.1@2891.67,5335.31 ; v1@2890.74,5297 2890.34,5296.6 2890.34,5264.03 R94.2@2891.67,5262.69
RD1_SLP_S0: R79.1 R93.2 U19.4 | length 320.3
  Top_SL w10: v1(3032.07,5149.96) 3032.07,5147.26 3034.35,5144.98 3034.35,5142.52 3060.72,5116.15 3060.72,5084.75 U19.4@3060.84,5084.62
  Signal_Layer w8: v1(2976.87,5297.31) 2976.87,5245.96 2989.09,5233.75 2989.09,5192.95 v1(3032.07,5149.96)
  Bottom_SL w8: R93.2@2977.28,5262.69 2977.46,5262.87 2977.46,5335.13 R79.1@2977.65,5335.31
RD1_SSEQ0_A0: R81.1 R95.2 U19.35 | length 505.3
  Top_SL w6: U19.35@3127.77,4978.32 3128.11,4978.66 v1(3186.84,4978.67)
  Signal_Layer w8: v1(3092.65,5297.35) 3092.14,5296.84 3092.14,5207.06 3138.2,5161 3138.2,4999.92 3159.8,4978.32 3186.49,4978.32 v1(3186.84,4978.67)
  Bottom_SL w6: R95.2@3091.42,5264.69 3092.03,5265.3 3092.03,5296.74 v1(3092.65,5297.35) 3092.65,5335.29 R81.1@3092.29,5335.64
RD1_SSEQ1_A1: R82.1 R96.2 U19.2 | length 309.5
  Top_SL w10: U19.2@3092.34,5084.62 v1(3092.34,5154.18)
  Signal_Layer w8: v1(3034.51,5297.31) 3034.51,5212.01 v1(3092.34,5154.18)
  Bottom_SL w6: R96.2@3034.35,5262.69 3034.66,5263 3034.66,5335 R82.1@3034.97,5335.31
RD1_VIO_SEL: R87.1 R101.2 U19.14 | length 445.9
  Top_SL w6: v1(2926.58,4980.82) 2928.89,4978.51 2977.98,4978.51 U19.14@2978.16,4978.32
  Signal_Layer w8: v1(2919.24,5297.31) 2919.24,4989.28 2926.58,4981.95 v1(2926.58,4980.82)
  Bottom_SL w8: R101.2@2920.21,5262.69 2919.72,5263.18 2919.72,5296.83 v1(2919.24,5297.31) 2919.79,5297.85 2919.79,5335.09 R87.1@2920.33,5335.64
RD2_CFG0: R36.1 R54.2 U3.3 | length 429.2
  Top_SL w8: U3.3@3075.86,1483.91 3075.86,1537.14 3101.39,1562.67 v1(3101.39,1562.81) ; R54.2@3268.21,1694.48 v1(3268.21,1726.8)
  Signal_Layer w8: v1(3101.39,1562.81) 3103.69,1565.1 3109.34,1565.1 3268.21,1723.97 v1(3268.21,1726.8)
  Bottom_SL w8: v1(3268.21,1726.8) 3269.18,1725.83 R36.1@3269.18,1689.99 ; v1@3269.18,1726.09 R54.2@3269.18,1759.87
RD2_CFG1: R37.1 R55.2 U3.4 | length 436.7
  Top_SL w8: R37.1@3053.17,1592.52 3054.44,1592.52 3058.23,1588.73 3058.23,1587.46 3065.34,1580.35 v1(3065.34,1553.48) 3063.04,1551.19 3063.04,1542.7 3060.11,1539.77 U3.4@3060.11,1483.91
  Signal_Layer w8: v1(3065.34,1553.48) 3065.34,1553.62 3151.31,1639.59 3156.87,1639.59 v1@3242.14,1724.86
  Bottom_SL w8: R37.1@3242.14,1688.62 R55.2@3242.14,1760.84
  other v1: 3241.7,1724.59
RD2_CTL0: R129.1 R152.2 | length 2872.8
  Top_SL w10: v1(2988.72,1160.14) 2988.72,1161.76 2991.15,1164.19 R152.2@2991.15,1187.74
  Signal_Layer w8: v1(2988.72,1160.14) 2925.44,1160.14 2860.79,1224.78 2860.79,1565.43 3090.85,1795.49 3578.36,1795.49 4457.23,2674.35 v1(4457.23,2930.21)
  Bottom_SL w8: v1(4457.23,2930.21) 4457.72,2930.71 4457.72,2966.55 R129.1@4458.22,2967.04
RD2_CTL1: R44.1 R123.2 R147.1 U3.23 | length 2817.9
  Top_SL w8: U3.23@3028.61,1255.56 3028.61,1227.88 3025.8,1225.07 3025.8,1203.57 3029.28,1200.09 3029.28,1177.71 3028.61,1177.04 3028.61,1169.6 3033.3,1164.91 3110.39,1164.91 3131.68,1186.21 v1(3131.68,1187.9)
  Signal_Layer w8: v1(3131.68,1187.9) 3131.68,1277.42 3076.7,1332.4 3076.7,1475.37 v1(3325.92,1724.59) ; v1@3325.89,1724.96 3365.03,1764.1 3612.93,1764.1 4517.53,2668.69 4517.53,2929.69 v1(4517,2930.21)
  Bottom_SL w8: v1@3325.89,1724.96 3326.14,1724.71 R44.1@3326.14,1688.62 ; v1@3326.14,1724.59 R123.2@3326.14,1760.57 ; v1(4517,2930.21) 4517.67,2930.89 4517.67,2963.15 R147.1@4518.35,2963.82
RD2_DEQ0: R38.1 R56.2 U3.38 | length 518
  Top_SL w8: U3.38@3127.04,1424.86 3158.3,1424.86 3160.8,1427.36 v1(3164.05,1427.36) ; R56.2@3353,1695.99 3353.5,1696.49 3353.5,1724.09 v1(3353.99,1724.59)
  Signal_Layer w8: v1(3164.05,1427.36) 3164.05,1430.6 3160.26,1434.39 3160.26,1531.64 v1@3354.14,1725.52
  Bottom_SL w8: R38.1@3354.14,1688.62 R56.2@3354.14,1759.57
RD2_DEQ1: R39.1 R57.2 U3.29 | length 698.4
  Top_SL w8: U3.29@3127.04,1283.12 3127.1,1283.06 3154.93,1283.06 v1(3155.24,1282.75) ; v1(3410.14,1724.59) R57.2@3410.14,1768.62
  Signal_Layer w8: v1(3155.24,1282.75) 3158.49,1282.75 3171.18,1295.43 3179.33,1295.43 3207.46,1323.57 3207.46,1522.84 v1@3410.14,1725.52
  Bottom_SL w8: R39.1@3410.14,1688.62 R57.2@3410.14,1759.57
RD2_DIR0: R34.1 R52.2 U3.8 | length 468.4
  Top_SL w8: v1(2923.55,1487.39) 2925.85,1485.09 2933.05,1485.09 2934.24,1483.91 U3.8@2997.12,1483.91
  Signal_Layer w8: v1(2923.55,1487.39) 2923.55,1490.64 2911.23,1502.96 2911.23,1534.01 v1@3101.81,1724.59
  Bottom_SL w8: R34.1@3101.81,1688.34 3101.81,1724.59 3101.98,1724.76 R52.2@3101.98,1760.4
  other v1: 3101.33,1724.59
RD2_DIR1: R35.1 R53.2 U3.11 | length 508.4
  Top_SL w8: v1(2931.26,1434.43) 2934.5,1434.43 2944.08,1424.86 U3.11@2977.43,1424.86
  Signal_Layer w8: v1(2931.26,1434.43) 2928.96,1436.73 2912.2,1436.73 2898.23,1450.7 2898.23,1549.56 v1(3073.26,1724.59)
  Bottom_SL w8: R35.1@3073.26,1688.34 v1(3073.26,1724.59) R53.2@3073.26,1760.4
RD2_FLIP: R148.1 R149.2 | length 2770.5
  Top_SL w10: v1(2916.5,1195.95) 2919.2,1195.95 2926.12,1189.04 2934.85,1189.04 R149.2@2936.15,1187.74
  Signal_Layer w8: v1(2916.5,1195.95) 2875.65,1236.79 2875.65,1557.34 3097.27,1778.96 3594.33,1778.96 4487.98,2672.61 v1(4487.98,2930.21)
  Bottom_SL w8: R148.1@4487.22,2967.16 4487.6,2966.78 4487.6,2930.6 v1(4487.98,2930.21)
RD2_I2C_EN: R40.1 R58.2 U3.17 | length 619.5
  Top_SL w8: v1(2938.4,1328.23) 2940.48,1330.3 2977.37,1330.3 U3.17@2977.43,1330.37
  Signal_Layer w8: v1(2938.4,1328.23) 2938.4,1329.23 2954.74,1345.57 2965.1,1345.57 2990.09,1370.56 2990.09,1531.31 3184.13,1725.35 v1(3184.13,1726.02)
  Bottom_SL w8: v1@3182.78,1726.09 v1@3184.46,1724.41 ; v1(3184.13,1726.02) 3186.14,1728.03 R58.2@3186.14,1760.59 ; v1@3185.55,1724.59 3186.14,1724 R40.1@3186.14,1688.62
RD2_SLP_S0: R50.1 R124.2 U3.7 | length 428.3
  Top_SL w8: v1(2958.09,1511.04) 2997.31,1511.04 3012.87,1495.49 U3.7@3012.87,1483.91
  Signal_Layer w8: v1(2958.09,1511.04) 2960.09,1513.04 2960.09,1554.54 3128.05,1722.5 v1@3128.05,1724.96
  Bottom_SL w8: v1@3128.05,1724.96 3129.09,1723.92 R50.1@3129.09,1689.99 ; v1@3130.14,1724.59 R124.2@3130.14,1760.4
  other v1: 3129.41,1724.59
RD2_SWAP: R33.1 R51.2 U3.5 | length 388.4
  Top_SL w8: v1(3040.18,1551.76) 3040.18,1548.51 3044.36,1544.33 U3.5@3044.36,1483.91
  Signal_Layer w8: v1(3040.18,1551.76) 3040.18,1555.01 3046.34,1561.16 3046.34,1561.35 3204.04,1719.06 3204.85,1719.06 3210.38,1724.59 v1(3213.63,1724.59)
  Bottom_SL w8: R33.1@3213.93,1689.07 3213.93,1724.68 3213.75,1724.86 3213.93,1725.05 R51.2@3213.93,1760.67
RD2_UEQ0_A0: R41.1 R59.2 U3.35 | length 591.7
  Top_SL w8: U3.35@3127.04,1377.61 3127.1,1377.55 3162.49,1377.55 v1(3162.8,1377.23) ; v1(3382.07,1724.59) R59.2@3382.07,1769.72
  Signal_Layer w8: v1(3162.8,1377.23) 3187.6,1402.03 3187.6,1530.5 v1@3382.14,1725.05
  Bottom_SL w8: R41.1@3382.14,1688.62 R59.2@3382.14,1760.59
RD2_UEQ0_A1: R42.1 R60.2 U3.2 | length 434.5
  Top_SL w8: U3.2@3091.61,1483.91 3091.61,1522.77 3097.04,1528.2 v1(3097.04,1531.45) ; R60.2@3297,1694.99 3297.42,1695.42 3297.42,1724.17 v1(3297.85,1724.59)
  Signal_Layer w8: v1(3097.04,1531.45) 3099.73,1531.45 3287.8,1719.52 3289.53,1719.52 3294.6,1724.59 v1(3297.85,1724.59)
  Bottom_SL w8: v1@3295.64,1727.36 3296.89,1726.11 R42.1@3296.89,1688.89 ; v1@3298.14,1724.86 R60.2@3298.14,1759.84
RD2_VIO_SEL: R43.1 R61.2 U3.14 | length 723
  Top_SL w8: v1(2927.34,1377.23) 2966.43,1377.23 2966.74,1377.55 2977.37,1377.55 U3.14@2977.43,1377.61 ; R61.2@3052.99,1621 3053.78,1621 3156.99,1724.21 v1(3156.99,1725.08)
  Signal_Layer w8: v1(2927.34,1377.23) 2943.82,1393.71 2962.9,1393.71 2977.09,1407.89 2977.09,1544.67 3156.99,1724.57 v1(3156.99,1725.08)
  Bottom_SL w8: v1@3154.99,1726.33 3158.14,1729.48 R61.2@3158.14,1760.57 ; v1(3156.99,1725.08) 3157.57,1724.51 3157.57,1690.35 R43.1@3157.21,1689.99
RST: C112.1 R127.2 S4.2 U36.38 | length 276.1
  Top_SL w8: U36.38@3875.82,439.98 3949.08,439.98 3957.34,431.72 3957.34,413.51 3985,385.85 R127.2@3985,372.07 3985,334.97 4018.41,301.56 S4.2@4054.08,301.56
RX1_US1_N: C76.2 J8_US1.B10 U15_US1.3@465.44,4736.87 | length 2658.5
  Top_SL w6.5: J8_US1.B10@288.66,4727.01 292.52,4727.01 302.01,4717.51 358.72,4717.51 365.19,4723.98 421.53,4723.98 434.41,4736.87 U15_US1.3@465.44,4736.87 467.65,4734.65 467.65,4727.24 471.46,4723.43 2623.3,4723.43 2803.88,4904.01 2838.88,4904.01 2842.69,4907.82 2842.69,4908.97 2845.74,4912.02 C76.2@2846.53,4912.02
RX1_US1_P: C77.2 J8_US1.B11 U15_US1.2@465.44,4697.5 | length 2658.5
  Top_SL w6.5: J8_US1.B11@288.66,4695.51 292.52,4695.51 302.01,4705.01 363.9,4705.01 370.37,4711.48 422.3,4711.48 436.29,4697.5 U15_US1.2@465.44,4697.5 467.65,4699.72 467.65,4707.13 471.46,4710.93 2628.48,4710.93 2809.06,4891.51 2838.45,4891.51 2842.26,4887.7 2842.26,4886.56 2845.31,4883.51 C77.2@2846.09,4883.51
RX1_US2_N: C32.2 J8_US2.B10 U15_US2.3@474.92,1238.68 | length 2630.8
  Top_SL w6.5: J8_US2.B10@288.66,1231.01 292.52,1231.01 302.01,1221.51 360.72,1221.51 364.56,1225.35 423.21,1225.35 436.54,1238.68 U15_US2.3@474.92,1238.68 477.14,1236.47 477.14,1231.15 483.04,1225.25 2740.22,1225.25 2816.58,1301.61 2856.7,1301.61 2860.51,1305.42 2860.51,1306.31 2863.56,1309.36 C32.2@2864.35,1309.36
RX1_US2_P: C34.2 J8_US2.B11 U15_US2.2@474.92,1199.32 | length 2630.9
  Top_SL w6.5: J8_US2.B11@288.66,1199.51 292.52,1199.51 302.01,1209.01 365.9,1209.01 369.74,1212.85 423.36,1212.85 436.9,1199.32 U15_US2.2@474.92,1199.32 477.14,1201.53 477.14,1206.85 483.04,1212.75 2745.4,1212.75 2821.76,1289.11 2856.7,1289.11 2860.51,1285.3 2860.51,1284.41 2863.56,1281.36 C34.2@2864.35,1281.36
RX2_US1_N: C69.2 J8_US1.A10 U12_US1.3@457,4863.63 | length 2564.7
  Top_SL w6.5: v1(2716.81,5004.7) 2720.47,5004.7 2726.87,5011.1 2784.52,5011.1 2790.04,5005.59 2838.94,5005.59 2842.75,5001.78 2842.75,5000.39 2845.79,4997.34 C69.2@2846.58,4997.34
  Bottom_SL w6.5: J8_US1.A10@359.92,4858.9 389.08,4858.9 404.09,4873.91 409.47,4873.91 419.75,4863.63 U12_US1.3@457,4863.63 469.87,4876.5 673.25,4876.5 772.75,4976 2676.83,4976 2703.71,5002.88 2714.99,5002.88 v1(2716.81,5004.7)
RX2_US1_P: C68.2 J8_US1.A11 U12_US1.2@457,4903 | length 2570.4
  Top_SL w6.5: v1(2716.82,5030.02) 2720.47,5030.02 2726.89,5023.6 2789.7,5023.6 2795.22,5018.09 2838.94,5018.09 2842.75,5021.89 2842.75,5023.29 2845.79,5026.34 C68.2@2846.58,5026.34
  Bottom_SL w6.5: J8_US1.A11@359.92,4878.58 391.09,4878.58 398.91,4886.41 404.66,4886.41 421.94,4903.69 U12_US1.2@457,4903.69 ; U12_US1.2@457,4903 471,4889 668.07,4889 767.57,4988.5 2671.65,4988.5 2698.53,5015.38 2701.68,5015.38 2716.32,5030.02 v1(2716.82,5030.02)
RX2_US2_N: C21.2 J8_US2.A10 U12_US2.3@468.92,1354.32 | length 2576.1
  Top_SL w6.5: v1(2759.96,1459.73) 2763.62,1459.73 2770.33,1466.45 2796.13,1466.45 2804.94,1457.64 2856.7,1457.64 2860.51,1453.83 2860.51,1452.41 2863.56,1449.36 C21.2@2864.35,1449.36
  Bottom_SL w6.5: J8_US2.A10@359.92,1362.9 363.51,1366.49 403.49,1366.49 404.6,1367.6 417.06,1367.6 429.83,1354.83 468.4,1354.83 U12_US2.3@468.92,1354.32 471.14,1356.53 471.14,1363.94 474.95,1367.75 553.2,1367.75 651.83,1466.38 2749.66,1466.38 2756.31,1459.73 v1(2759.96,1459.73)
RX2_US2_P: C18.2 J8_US2.A11 U12_US2.2@468.92,1393.68 | length 2576.5
  Top_SL w6.5: v1(2760.26,1485.09) 2763.66,1485.09 2770.81,1477.95 2800.89,1477.95 2809.7,1469.14 2856.99,1469.14 2860.79,1472.95 2860.79,1474.37 2863.84,1477.42 C18.2@2864.63,1477.42
  Bottom_SL w6.5: J8_US2.A11@359.92,1382.58 363.51,1378.99 398.31,1378.99 399.42,1380.1 417.26,1380.1 430.85,1393.68 U12_US2.2@468.92,1393.68 471.14,1391.47 471.14,1384.06 474.95,1380.25 548.02,1380.25 646.65,1478.88 2750.39,1478.88 2756.6,1485.09 v1(2760.26,1485.09)
SSRX1_N: C76.1 U19.18 | length 118.3
  Top_SL w6.5: C76.1@2868.57,4912.02 2869.36,4912.02 2872.41,4908.97 2872.41,4907.82 2876.22,4904.01 2912.16,4904.01 2919.3,4911.15 2935.31,4911.15 2937.87,4913.7 2967.29,4913.7 2968.23,4914.64 2977.48,4914.64 U19.18@2978.16,4915.33
SSRX1_P: C77.1 U19.19 | length 118.7
  Top_SL w6.5: C77.1@2868.14,4883.51 2868.93,4883.51 2871.98,4886.56 2871.98,4887.7 2875.79,4891.51 2917.34,4891.51 2924.48,4898.65 2940.49,4898.65 2943.05,4901.2 2967.29,4901.2 2968.23,4900.27 2977.48,4900.27 U19.19@2978.16,4899.58
SSRX2_N: C69.1 U19.13 | length 118.5
  Top_SL w6.5: C69.1@2868.63,4997.34 2869.42,4997.34 2872.47,5000.39 2872.47,5001.78 2876.27,5005.59 2927.62,5005.59 2937.52,4995.69 2967.29,4995.69 2968.23,4994.76 2977.48,4994.76 U19.13@2978.16,4994.07
SSRX2_P: C68.1 U19.12 | length 118.5
  Top_SL w6.5: C68.1@2868.63,5026.34 2869.42,5026.34 2872.47,5023.29 2872.47,5021.89 2876.27,5018.09 2932.8,5018.09 2942.7,5008.19 2967.29,5008.19 2968.23,5009.13 2977.48,5009.13 U19.12@2978.16,5009.82
SSTX1_N: C78.1 U19.15 | length 114.5
  Top_SL w6.5: C78.1@2868.63,4968.48 2869.42,4968.48 2872.47,4965.43 2872.47,4964.47 2876.27,4960.66 2901.88,4960.66 2902.68,4961.45 2948.43,4961.45 2948.93,4960.95 2967.29,4960.95 2968.23,4961.89 2977.48,4961.89 U19.15@2978.16,4962.57
SSTX1_P: C79.1 U19.16 | length 114.5
  Top_SL w6.5: C79.1@2868.63,4940.34 2869.42,4940.34 2872.47,4943.39 2872.47,4944.35 2876.27,4948.16 2907.06,4948.16 2907.85,4948.95 2943.25,4948.95 2943.75,4948.45 2967.29,4948.45 2968.23,4947.51 2977.48,4947.51 U19.16@2978.16,4946.82
SSTX2_N: C71.1 U19.10 | length 121.9
  Top_SL w6.5: C71.1@2868.63,5054.34 2869.42,5054.34 2872.47,5057.39 2872.47,5058.28 2876.27,5062.09 2914.89,5062.09 2934.04,5042.94 2967.29,5042.94 2968.23,5042 2977.48,5042 U19.10@2978.16,5041.31
SSTX2_P: C70.1 U19.9 | length 121.9
  Top_SL w6.5: C70.1@2868.63,5082.34 2869.42,5082.34 2872.47,5079.29 2872.47,5078.39 2876.27,5074.59 2920.07,5074.59 2939.22,5055.44 2967.29,5055.44 2968.23,5056.37 2977.48,5056.37 U19.9@2978.16,5057.06
TX1_US1_N: C78.2 J8_US1.A3 U14_US1.2@473.46,4736.17 | length 2613.5
  Top_SL w6.5: v1(2778.72,4957.19) 2782.38,4957.19 2788.62,4950.95 2806.14,4950.95 2815.85,4960.66 2838.94,4960.66 2842.75,4964.47 2842.75,4965.43 2845.79,4968.48 C78.2@2846.58,4968.48
  Bottom_SL w6.5: J8_US1.A3@359.92,4721.1 363.51,4717.51 374.26,4717.51 390.07,4717.51 396.52,4723.95 421.49,4723.95 433.91,4736.37 473.26,4736.37 475.68,4733.95 475.68,4726.54 479.49,4722.73 627.81,4722.73 758.9,4853.82 2671.7,4853.82 2760.6,4942.72 2763.45,4942.72 2777.92,4957.19 v1(2778.72,4957.19)
TX1_US1_P: C79.2 J8_US1.A2 U14_US1.3@473.46,4696.8 | length 2609.1
  Top_SL w6.5: v1(2778.73,4932.19) 2782.39,4932.19 2788.64,4938.45 2811.32,4938.45 2821.03,4948.16 2838.94,4948.16 2842.75,4944.35 2842.75,4943.39 2845.79,4940.34 C79.2@2846.58,4940.34
  Bottom_SL w6.5: J8_US1.A2@359.92,4701.42 363.51,4705.01 377.07,4705.01 395.25,4705.01 401.69,4711.45 422.33,4711.45 436.99,4696.8 U14_US1.3@473.46,4696.8 475.68,4699.02 475.68,4706.42 479.49,4710.23 632.99,4710.23 764.08,4841.32 2676.88,4841.32 2765.78,4930.22 2776.76,4930.22 v1(2778.73,4932.19)
TX1_US2_N: C28.2 J8_US2.A3 U14_US2.2@473.82,1238.34 | length 2585.7
  Top_SL w6.5: v1(2792.1,1356.16) 2795.75,1356.16 2802.4,1349.5 2829.51,1349.5 2837.61,1357.61 2856.7,1357.61 2860.51,1361.42 2860.51,1362.31 2863.56,1365.36 C28.2@2864.35,1365.36
  Bottom_SL w6.5: J8_US2.A3@359.92,1225.1 363.47,1221.56 419.42,1221.56 436.2,1238.34 U14_US2.2@473.82,1238.34 476.04,1236.12 476.04,1230.81 481.94,1224.91 717.6,1224.91 842.7,1350 2782.29,1350 2788.44,1356.16 v1(2792.1,1356.16)
TX1_US2_P: C30.2 J8_US2.A2 U14_US2.3@473.82,1198.97 | length 2585.3
  Top_SL w6.5: v1(2792.83,1329.51) 2795.9,1329.51 2803.39,1337 2834.69,1337 2842.79,1345.11 2856.7,1345.11 2860.51,1341.3 2860.51,1340.41 2863.56,1337.36 C30.2@2864.35,1337.36
  Bottom_SL w6.5: J8_US2.A2@359.92,1205.42 363.56,1209.06 421.94,1209.06 432.03,1198.97 U14_US2.3@473.82,1198.97 476.04,1201.19 476.04,1208.6 479.85,1212.41 722.78,1212.41 847.87,1337.5 2782.27,1337.5 2790.26,1329.51 v1(2792.83,1329.51)
TX2_US1_N: C71.2 J8_US1.B3 U13_US1.2@457,4863.63 | length 2672.3
  Top_SL w6.5: J8_US1.B3@288.66,4852.99 292.52,4852.99 302.01,4862.49 352.64,4862.49 366.78,4876.63 406.76,4876.63 419.75,4863.63 U13_US1.2@457,4863.63 459.22,4865.85 459.22,4871.16 465.12,4877.07 559.78,4877.07 757.12,5074.41 2724.05,5074.41 2736.37,5062.09 2838.94,5062.09 2842.75,5058.28 2842.75,5057.39 2845.79,5054.34 C71.2@2846.58,5054.34
TX2_US1_P: C70.2 J8_US1.B2 U13_US1.3@457,4903 | length 2672.7
  Top_SL w6.5: J8_US1.B2@288.66,4884.49 292.52,4884.49 302.01,4874.99 347.47,4874.99 361.6,4889.13 407.38,4889.13 421.25,4903 U13_US1.3@457,4903 459.22,4900.78 459.22,4895.47 465.12,4889.57 554.6,4889.57 751.94,5086.91 2729.23,5086.91 2741.55,5074.59 2838.94,5074.59 2842.75,5078.39 2842.75,5079.29 2845.79,5082.34 C70.2@2846.58,5082.34
TX2_US2_N: C26.2 J8_US2.B3 U13_US2.2@468.9,1354.07 | length 2621.3
  Top_SL w6.5: J8_US2.B3@288.66,1356.99 292.52,1356.99 302.01,1366.49 364.25,1366.49 365.26,1367.5 417.16,1367.5 430.6,1354.07 U13_US2.2@468.9,1354.07 471.12,1356.28 471.12,1363.69 474.93,1367.5 615.69,1367.5 651.7,1403.51 2773.34,1403.51 2780.73,1410.91 2816.12,1410.91 2825.92,1401.11 2856.7,1401.11 2860.51,1397.3 2860.51,1396.41 2863.56,1393.36 C26.2@2864.35,1393.36
TX2_US2_P: C24.2 J8_US2.B2 U13_US2.3@468.9,1393.43 | length 2621.3
  Top_SL w6.5: J8_US2.B2@288.66,1388.49 292.52,1388.49 302.01,1378.99 359.08,1378.99 360.09,1380 417.16,1380 430.6,1393.43 U13_US2.3@468.9,1393.43 471.12,1391.22 471.12,1383.81 474.93,1380 610.51,1380 646.52,1416.01 2768.16,1416.01 2775.56,1423.41 2821.3,1423.41 2831.1,1413.61 2856.7,1413.61 2860.51,1417.42 2860.51,1418.31 2863.56,1421.36 C24.2@2864.35,1421.36
URX1_N: C32.1 U3.18 | length 100.2
  Top_SL w6.5: C32.1@2886.39,1309.36 2887.18,1309.36 2890.23,1306.31 2890.23,1305.42 2894.04,1301.61 2919.97,1301.61 2921.23,1302.87 2938.85,1302.87 2948.98,1313 2966.56,1313 2967.5,1313.93 2976.75,1313.93 U3.18@2977.43,1314.62
URX1_P: C34.1 U3.19 | length 100.2
  Top_SL w6.5: C34.1@2886.39,1281.36 2887.18,1281.36 2890.23,1284.41 2890.23,1285.3 2894.04,1289.11 2925.15,1289.11 2926.41,1290.37 2944.03,1290.37 2954.15,1300.5 2966.56,1300.5 2967.5,1299.56 2976.75,1299.56 U3.19@2977.43,1298.87
URX2_N: C21.1 U3.10 | length 101.7
  Top_SL w6.5: C21.1@2886.39,1449.36 2887.18,1449.36 2890.23,1452.41 2890.23,1453.33 2894.04,1457.14 2910.31,1457.14 2914.77,1452.68 2938.82,1452.68 2949.27,1442.23 2966.56,1442.23 2967.5,1441.29 2976.75,1441.29 U3.10@2977.43,1440.6
URX2_P: C18.1 U3.9 | length 101.4
  Top_SL w6.5: C18.1@2886.68,1477.42 2887.47,1477.42 2890.51,1474.37 2890.51,1473.45 2894.32,1469.64 2915.49,1469.64 2919.95,1465.18 2943.99,1465.18 2954.45,1454.73 2966.56,1454.73 2967.5,1455.66 2976.75,1455.66 U3.9@2977.43,1456.35
US_CC1_US1: J8_US1.A5 TP18_US1.1 | length 199.4
  Top_SL w6: v1(536.64,4760.47) TP18_US1.1@567.15,4760.47
  Bottom_SL w6: J8_US1.A5@359.92,4760.47 v1@528.77,4760.47
US_CC1_US2: J8_US2.A5 TP18_US2.1 | length 251.1
  Top_SL w10: v1(567.8,1246.76) TP18_US2.1@603.71,1246.76
  Bottom_SL w10: J8_US2.A5@359.92,1264.47 361.81,1262.58 373.65,1262.58 374.56,1261.68 376.67,1261.68 377.88,1260.47 475.33,1260.47 489.04,1246.76 v1(567.8,1246.76)
US_CC2_US1: J8_US1.B5 TP17_US1.1 | length 423.4
  Top_SL w6.5: TP17_US1.1@227,4445.69 227,4797.47 251.02,4821.5 J8_US1.B5@288.66,4821.5
US_CC2_US2: J8_US2.B5 TP17_US2.1 | length 364.6
  Top_SL w6.5: TP17_US2.1@247.32,978 247.32,1284.16 J8_US2.B5@288.66,1325.5
UTX1_N: C28.1 U3.15 | length 96.5
  Top_SL w6.5: C28.1@2886.39,1365.36 2887.18,1365.36 2890.23,1362.31 2890.23,1361.42 2894.04,1357.61 2924.29,1357.61 2925.67,1358.98 2934.9,1358.98 2936.16,1360.24 2966.56,1360.24 2967.5,1361.18 2976.75,1361.18 U3.15@2977.43,1361.86
UTX1_P: C30.1 U3.16 | length 96.5
  Top_SL w6.5: C30.1@2886.39,1337.36 2887.18,1337.36 2890.23,1340.41 2890.23,1341.3 2894.04,1345.11 2929.47,1345.11 2930.84,1346.48 2940.08,1346.48 2941.33,1347.74 2966.56,1347.74 2967.5,1346.8 2976.75,1346.8 U3.16@2977.43,1346.12
UTX2_N: C26.1 U3.13 | length 98
  Top_SL w6.5: C26.1@2886.39,1393.36 2887.18,1393.36 2890.23,1396.41 2890.23,1397.3 2894.04,1401.11 2929.92,1401.11 2936.05,1394.98 2966.56,1394.98 2967.5,1394.05 2976.75,1394.05 U3.13@2977.43,1393.36
UTX2_P: C24.1 U3.12 | length 98
  Top_SL w6.5: C24.1@2886.39,1421.36 2887.18,1421.36 2890.23,1418.31 2890.23,1417.42 2894.04,1413.61 2935.1,1413.61 2941.23,1407.48 2966.56,1407.48 2967.5,1408.42 2976.75,1408.42 U3.12@2977.43,1409.11
VBUS_DS1: C88_DS1.2 C118_DS1.1 C119_DS1.1 C120_DS1.1 C121_DS1.1 D13_DS1.1 J9_DS1.A4 J9_DS1.A9 J9_DS1.B4 J9_DS1.B9 L2_DS1.2 TP10_DS1.1 U21_DS1.4 U21_DS1.5 U21_DS1.6 | length 1155.8
  Top_SL w12: J9_DS1.A4@5254.91,4653.06 J9_DS1.B9@5298.61,4653.06 ; J9_DS1.A9@5254.91,4751.48 J9_DS1.B4@5298.61,4751.48
  POWER w25: v1(5197.62,4589.53) 5199.92,4591.83 5235.41,4591.83 J9_DS1.B9@5298.61,4655.03 5298.5,4655.14 5287.15,4655.14 5268.31,4673.97 5268.31,4730.57 5287.15,4749.4 5298.5,4749.4 J9_DS1.B4@5298.61,4749.51 5235.95,4812.18 v1(5204.37,4812.18)
  Bottom_SL w30: TP10_DS1.1@4831.4,5078 4831.4,5066.1 4928.5,4969 5189,4969 5205.12,4952.88 5205.12,4812.93 v1(5204.37,4812.18) ; L2_DS1.2@5195.66,4476.8 5197.62,4478.77 5197.62,4520.5 5197.47,4520.65 5197.47,4560.35 C121_DS1.1@5197.62,4560.51 v1(5197.62,4589.53)
VBUS_DS2: C88_DS2.2 C118_DS2.1 C119_DS2.1 C120_DS2.1 C121_DS2.1 D13_DS2.1 J9_DS2.A4 J9_DS2.A9 J9_DS2.B4 J9_DS2.B9 L2_DS2.2 TP10_DS2.1 U21_DS2.4 U21_DS2.5 U21_DS2.6 | length 1075.4
  Top_SL w12: J9_DS2.A4@5255.25,1227.55 5296.98,1227.55 J9_DS2.B9@5298.95,1229.52 ; J9_DS2.A9@5255.25,1325.98 J9_DS2.B4@5296.22,1325.98
  POWER w25: v1(5209.76,1167.37) 5236.8,1167.37 5292.57,1223.14 J9_DS2.B9@5298.95,1229.52 5298.84,1229.63 5286.08,1229.63 5261.82,1253.89 5261.82,1299.63 5286.08,1323.9 5298.84,1323.9 J9_DS2.B4@5298.95,1324.01 5292.57,1330.39 5245.69,1377.27 5220.42,1377.27 v1(5214.69,1383)
  Bottom_SL w30: TP10_DS2.1@4916.35,1559.47 5030.23,1559.47 5030.46,1559.24 5081.11,1559.24 5148.41,1559.24 5174,1559.24 5203.18,1559.24 5214.69,1547.74 v1(5214.69,1383) ; C88_DS2.2@5197.95,1014.53 5198.64,1014.53 5207.8,1023.68 C118_DS2.1@5207.8,1115.2 5207.8,1165.4 v1(5209.76,1167.37)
